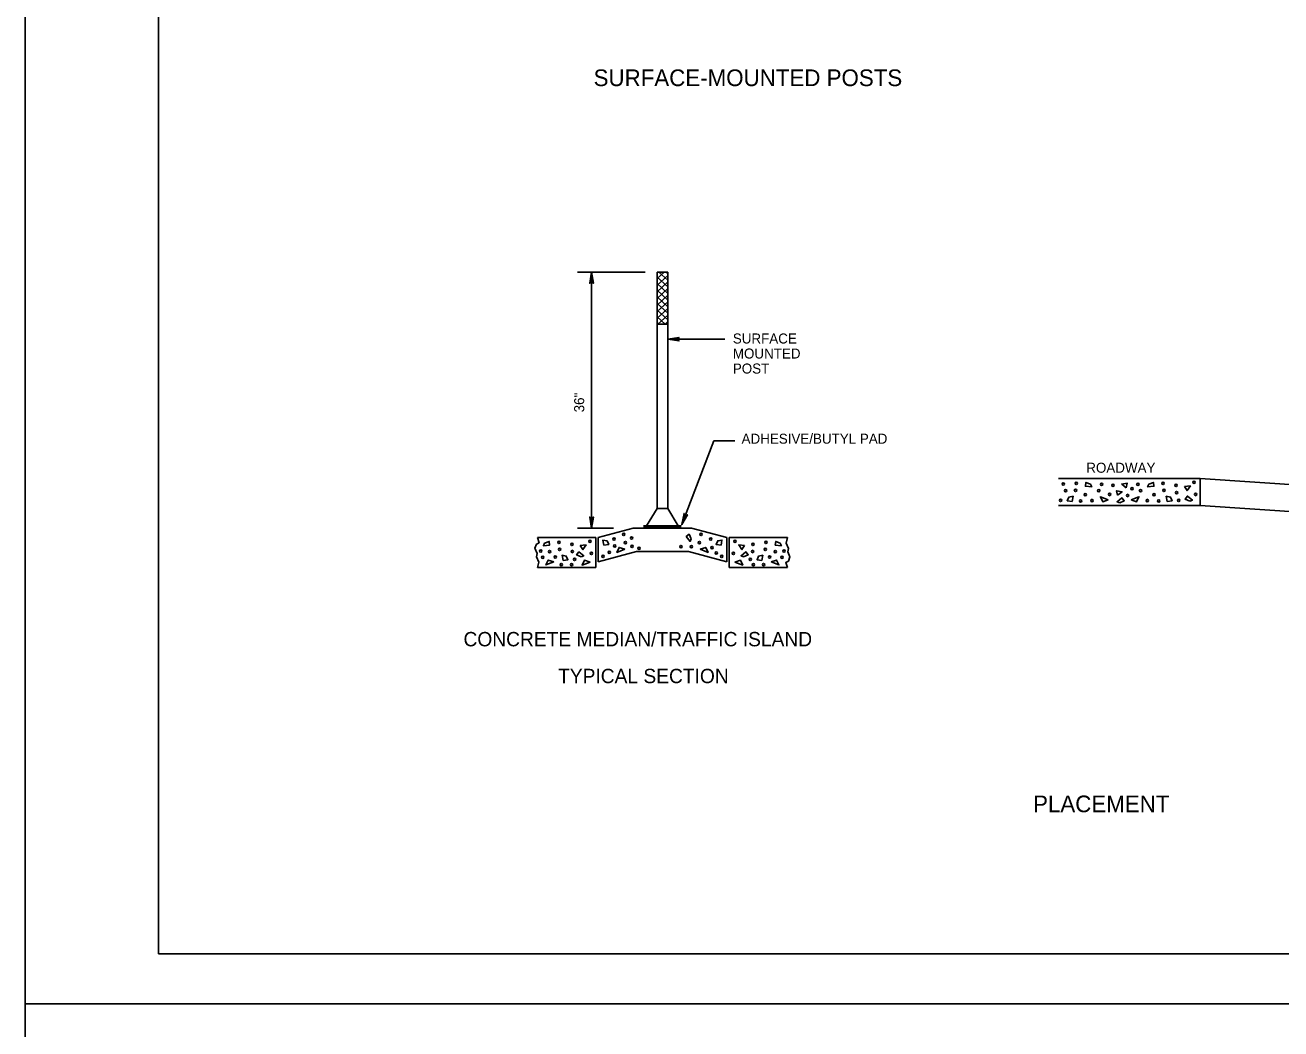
# Model space of a CAD drawing. Extents: x 640253 to 641999, y 298458 to 299646.
# Drawn here: x 640253.3 to 640629.6, y 299044.1 to 299344.9 of the extents above; entities that cross this region are included whole.
import ezdxf

# ---------------------------------------------------------------- set-up
doc = ezdxf.new("R2010")
doc.units = 0
for name, color, linetype in [('1', 7, 'Continuous'), ('2', 7, 'Continuous'), ('PLT-BNDY', 7, 'Continuous')]:
    doc.layers.add(name, color=color, linetype=linetype)

msp = doc.modelspace()

# ---------------------------------------------------------------- linework, layer by layer
at = {"layer": '1'}
for p, q in [((640293.31, 299630.63), (640293.31, 299066.63)), ((641079.31, 299066.63), (640293.31, 299066.63)), ((640293.31, 299066.63), (640879.31, 299066.63))]:
    msp.add_line(p, q, dxfattribs=at)
at = {"layer": '2'}
for p, q in [((640418.89, 299270.87), (640439.12, 299270.87)), ((640423.06, 299194.13), (640423.06, 299270.87)), ((640442.69, 299270.87), (640445.92, 299270.87)), ((640442.69, 299255.28), (640442.69, 299270.87)), ((640442.69, 299268.93), (640444.82, 299270.87)), ((640442.69, 299266.95), (640445.92, 299269.89)), ((640445.92, 299266.46), (640442.69, 299269.4)), ((640442.69, 299264.97), (640445.92, 299267.91)), ((640445.92, 299264.47), (640442.69, 299267.41)), ((640445.92, 299268.43), (640443.24, 299270.87)), ((640445.92, 299270.41), (640445.42, 299270.87)), ((640445.92, 299255.28), (640445.92, 299270.87)), ((640442.69, 299262.99), (640445.92, 299265.93)), ((640445.92, 299262.5), (640442.69, 299265.43)), ((640442.69, 299261.01), (640445.92, 299263.95)), ((640445.92, 299260.51), (640442.69, 299263.45)), ((640442.69, 299259.03), (640445.92, 299261.97)), ((640445.92, 299258.53), (640442.69, 299261.47)), ((640442.69, 299257.05), (640445.92, 299259.99)), ((640445.92, 299256.55), (640442.69, 299259.49)), ((640445.14, 299255.28), (640442.69, 299257.52)), ((640442.92, 299255.28), (640445.92, 299258.01)), ((640442.96, 299255.28), (640442.69, 299255.53)), ((640442.69, 299255.28), (640445.92, 299255.28)), ((640442.69, 299200.02), (640442.69, 299255.28)), ((640445.1, 299255.28), (640445.92, 299256.03)), ((640445.92, 299200.02), (640445.92, 299255.28)), ((640445.92, 299250.8), (640463, 299250.8)), ((640450.08, 299195.24), (640459.71, 299220.35)), ((640459.71, 299220.35), (640465.99, 299220.35)), ((640562.97, 299208.99), (640605.44, 299208.99)), ((640605.44, 299200.94), (640605.44, 299208.99)), ((640605.44, 299208.99), (640714.64, 299201.64)), ((640439.54, 299194.82), (640442.69, 299200.02)), ((640442.69, 299200.02), (640445.92, 299200.02)), ((640449.07, 299194.82), (640445.92, 299200.02)), ((640562.97, 299200.94), (640605.44, 299200.94)), ((640605.44, 299200.94), (640714.64, 299193.59)), ((640418.89, 299194.13), (640429.65, 299194.13)), ((640435.56, 299194.13), (640425.06, 299191.32)), ((640435.56, 299194.13), (640453.06, 299194.13)), ((640438.66, 299194.65), (640449.95, 299194.65)), ((640438.66, 299194.48), (640449.95, 299194.48)), ((640438.66, 299194.31), (640449.95, 299194.31)), ((640438.67, 299194.82), (640449.94, 299194.82)), ((640453.06, 299194.13), (640463.56, 299191.32)), ((640406.86, 299191.32), (640424.36, 299191.32)), ((640424.36, 299191.32), (640424.36, 299182.32)), ((640425.06, 299191.32), (640425.06, 299184.07)), ((640463.56, 299191.32), (640463.56, 299184.07)), ((640464.26, 299191.32), (640464.26, 299182.32)), ((640481.76, 299191.32), (640464.26, 299191.32)), ((640436.49, 299187.13), (640425.06, 299184.07)), ((640436.49, 299187.13), (640452.13, 299187.13)), ((640452.13, 299187.13), (640463.56, 299184.07)), ((640406.86, 299182.32), (640424.36, 299182.32)), ((640481.76, 299182.32), (640464.26, 299182.32))]:
    msp.add_line(p, q, dxfattribs=at)
for points in [[(640422.66, 299267.67), (640422.89, 299267.79), (640423.06, 299270.87), (640422.66, 299267.67), (640422.52, 299267.51), (640423.06, 299270.87), (640423.21, 299267.79), (640423.44, 299267.68), (640423.06, 299270.87), (640423.6, 299267.51), (640423.44, 299267.68)], [(640449.12, 299250.39), (640449, 299250.62), (640445.92, 299250.8), (640449.12, 299250.39), (640449.28, 299250.25), (640445.92, 299250.8), (640449, 299250.95), (640449.11, 299251.17), (640445.92, 299250.8), (640449.28, 299251.33), (640449.11, 299251.17)], [(640423.46, 299197.33), (640423.23, 299197.21), (640423.06, 299194.13), (640423.46, 299197.33), (640423.6, 299197.49), (640423.06, 299194.13), (640422.91, 299197.21), (640422.68, 299197.32), (640423.06, 299194.13), (640422.53, 299197.49), (640422.68, 299197.32)], [(640451.6, 299198.07), (640451.34, 299198.05), (640450.08, 299195.24), (640451.6, 299198.07), (640451.79, 299198.18), (640450.08, 299195.24), (640451.04, 299198.16), (640450.87, 299198.35), (640450.08, 299195.24), (640450.78, 299198.56), (640450.87, 299198.35)], [(640406.86, 299191.32), (640407.34, 299189.77), (640406.52, 299189.35), (640406.11, 299188.12), (640406.73, 299186.57), (640406.52, 299185.54), (640407.24, 299184), (640406.86, 299182.32)], [(640481.76, 299182.32), (640481.27, 299183.88), (640482.09, 299184.29), (640482.5, 299185.52), (640481.88, 299187.07), (640482.09, 299188.1), (640481.37, 299189.65), (640481.76, 299191.32)]]:
    msp.add_lwpolyline(points, dxfattribs=at)
for points in [[(640572.62, 299207.3), (640571.23, 299207.85), (640571.09, 299206.73), (640572.96, 299206.53)], [(640583.33, 299206.25), (640583.63, 299207.63), (640581.96, 299207.34)], [(640590.06, 299207.3), (640591.45, 299207.85), (640591.59, 299206.73), (640589.72, 299206.53)], [(640567.08, 299202.17), (640565.63, 299202.37), (640566.11, 299203.48), (640567.37, 299203.69)], [(640577.93, 299202.64), (640576.27, 299202.09), (640575.57, 299203.55)], [(640580.68, 299203.99), (640580.39, 299205.37), (640582.06, 299205.07)], [(640584.74, 299202.64), (640586.41, 299202.09), (640587.11, 299203.55)], [(640595.59, 299202.17), (640597.05, 299202.37), (640596.57, 299203.48), (640595.31, 299203.69)], [(640600.78, 299206.59), (640601.54, 299205.41), (640602.52, 299206.8)], [(640602.33, 299202.27), (640600.96, 299202.86), (640601.65, 299203.75), (640603.12, 299202.57)], [(640581.34, 299201.76), (640582.71, 299202.35), (640582.02, 299203.23), (640580.55, 299202.06)], [(640452.9, 299190.96), (640452.31, 299192.33), (640451.43, 299191.65), (640452.6, 299190.17)], [(640408.98, 299189.62), (640410.37, 299190.18), (640410.51, 299189.06), (640408.63, 299188.86)], [(640419.7, 299188.92), (640420.46, 299187.74), (640421.43, 299189.13)], [(640426.76, 299189.08), (640428.21, 299189.28), (640427.73, 299190.4), (640426.48, 299190.6)], [(640433.01, 299187.82), (640431.34, 299188.37), (640430.65, 299186.91)], [(640455.61, 299187.82), (640457.27, 299188.37), (640457.97, 299186.91)], [(640461.86, 299189.08), (640460.4, 299189.28), (640460.88, 299190.4), (640462.13, 299190.6)], [(640468.92, 299188.92), (640468.15, 299187.74), (640467.18, 299189.13)], [(640479.63, 299189.62), (640478.25, 299190.18), (640478.1, 299189.06), (640479.98, 299188.86)], [(640411.75, 299184.05), (640410.08, 299184.61), (640409.38, 299183.15)], [(640414.51, 299184.49), (640415.97, 299184.7), (640415.48, 299185.81), (640414.23, 299186.02)], [(640419.96, 299185.58), (640418.59, 299186.17), (640419.27, 299187.06), (640420.75, 299185.88)], [(640422.61, 299184), (640420.95, 299184.56), (640420.25, 299183.1)], [(640466, 299184), (640467.67, 299184.56), (640468.36, 299183.1)], [(640468.65, 299185.58), (640470.02, 299186.17), (640469.34, 299187.06), (640467.86, 299185.88)], [(640474.1, 299184.49), (640472.65, 299184.7), (640473.13, 299185.81), (640474.38, 299186.02)], [(640476.86, 299184.05), (640478.53, 299184.61), (640479.23, 299183.15)]]:
    msp.add_lwpolyline(points, close=True, dxfattribs=at)
for centre in [(640564.41, 299207.36), (640568.32, 299207.56), (640575.9, 299207.33), (640579.29, 299207.02), (640586.78, 299207.33), (640594.36, 299207.56), (640598.26, 299206.95), (640603.65, 299207.9), (640565.11, 299205.35), (640568.1, 299205.48), (640571, 299204.18), (640575.09, 299205.35), (640578.32, 299204.24), (640583.7, 299203.94), (640585.06, 299205.95), (640587.58, 299205.35), (640591.67, 299204.18), (640594.58, 299205.48), (640598.39, 299204.83), (640604.11, 299204.24), (640563.64, 299202.48), (640569.63, 299202.32), (640573.06, 299202.44), (640589.62, 299202.44), (640593.05, 299202.32), (640599.04, 299202.48), (640432.7, 299192.29), (640455.91, 299192.29), (640413.27, 299189.89), (640417.18, 299189.28), (640422.57, 299190.23), (640429.82, 299190.9), (640430.03, 299188.84), (640433.22, 299189.82), (640435.07, 299191.16), (640435.22, 299188.68), (640437.33, 299188.12), (640449.84, 299188.63), (640452.98, 299188.58), (640455.4, 299189.82), (640458.79, 299190.9), (640459.2, 299188.33), (640466.05, 299190.23), (640471.43, 299189.28), (640475.34, 299189.89), (640407.84, 299187.27), (640408.44, 299185.43), (640410.49, 299187.12), (640412.17, 299185.48), (640413.5, 299187.81), (640417.3, 299187.16), (640417.96, 299184.81), (640423.03, 299186.57), (640426.53, 299185.7), (640428.38, 299186.93), (640460.44, 299186.73), (640462.09, 299185.7), (640465.59, 299186.57), (640470.65, 299184.81), (640471.31, 299187.16), (640475.12, 299187.81), (640476.44, 299185.48), (640478.12, 299187.12), (640480.18, 299185.43), (640480.77, 299187.27), (640413.97, 299183.26), (640417.06, 299183.21), (640471.56, 299183.21), (640474.64, 299183.26)]:
    msp.add_circle(centre, 0.352, dxfattribs=at)
at = {"layer": 'PLT-BNDY'}
for points in [[(640253.31, 299645.63), (641094.31, 299645.63), (641094.31, 299051.63), (640253.31, 299051.63)], [(640253.31, 299051.63), (641094.31, 299051.63), (641094.31, 298457.63), (640253.31, 298457.63)]]:
    msp.add_lwpolyline(points, close=True, dxfattribs=at)

# ---------------------------------------------------------------- texts
at = {"layer": '2'}
for s, height, p in [('SURFACE-MOUNTED POSTS', 5, (640423.68, 299326.6)), ('SURFACE', 3, (640465.41, 299249.48)), ('MOUNTED', 3, (640465.41, 299244.98)), ('POST', 3, (640465.41, 299240.48)), ('ADHESIVE/BUTYL PAD', 3, (640468.03, 299219.46)), ('ROADWAY', 3, (640571.33, 299210.76)), ('CONCRETE MEDIAN/TRAFFIC ISLAND', 4.3, (640384.69, 299158.75)), ('TYPICAL SECTION', 4.3, (640413.04, 299147.71)), ('PLACEMENT', 5, (640555.38, 299109.04))]:
    msp.add_text(s, height=height, dxfattribs=at).set_placement(p)
msp.add_text('36"', height=3, rotation=90, dxfattribs=at).set_placement((640420.86, 299228.85))

doc.saveas('drawing.dxf')
